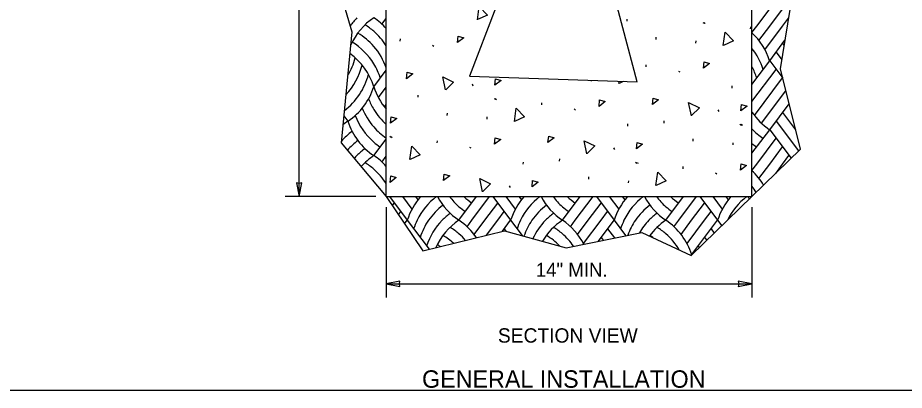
# Model space of a CAD drawing. Extents: x 99862 to 103151, y 100000 to 102076.
# Drawn here: x 101489 to 102507, y 100000 to 100427 of the extents above; entities that cross this region are included whole.
import ezdxf

# ---------------------------------------------------------------- set-up
doc = ezdxf.new("R2010")
doc.units = 0
for name, color, linetype in [('Level 1', 7, 'Continuous'), ('Level 15', 7, 'Continuous'), ('Level 17', 7, 'Continuous'), ('Level 20', 7, 'Continuous'), ('Level 21', 7, 'Continuous'), ('Level 24', 7, 'Continuous'), ('Level 25', 7, 'Continuous'), ('Level 26', 7, 'Continuous')]:
    doc.layers.add(name, color=color, linetype=linetype)

msp = doc.modelspace()

# ---------------------------------------------------------------- linework, layer by layer
at = {"layer": 'Level 1'}
msp.add_lwpolyline([(99862, 99999.5), (103151, 99999.5), (103151, 102075.5), (99862, 102075.5)], close=True, dxfattribs=at)
at = {"layer": 'Level 15'}
for p, q in [((101812.2, 100221.9), (101812.2, 100912.5)), ((101900.2, 100221.9), (101796.2, 100221.9)), ((101912.2, 100209.9), (101912.2, 100105.9)), ((102332.2, 100209.9), (102332.2, 100105.9)), ((101912.2, 100121.9), (102332.2, 100121.9))]:
    msp.add_line(p, q, dxfattribs=at)
for points in [[(101812.2, 100221.9), (101815.2, 100237.6), (101812.2, 100236.9), (101809.1, 100237.6)], [(101912.2, 100121.9), (101927.9, 100118.8), (101927.2, 100121.9), (101927.9, 100125)], [(102332.2, 100121.9), (102316.4, 100125), (102317.2, 100121.9), (102316.4, 100118.8)]]:
    msp.add_lwpolyline(points, close=True, dxfattribs=at)
at = {"layer": 'Level 17'}
for p, q in [((101912.2, 100221.9), (101912.2, 100731.9)), ((102332.2, 100221.9), (102332.2, 100731.9)), ((101912.2, 100221.9), (102332.2, 100221.9))]:
    msp.add_line(p, q, dxfattribs=at)
at = {"layer": 'Level 24'}
for points in [[(102332.2, 100221.9), (102387.8, 100276.5), (102364.8, 100368.6), (102384.3, 100489), (102366.6, 100591.7), (102387.8, 100729.7), (102366.6, 100795.2), (102391.4, 100912.1), (102348.9, 100974), (102350.7, 101089.1), (102318.8, 101124.5), (102354.2, 101152.8), (102428.5, 101131.6), (102490.5, 101205.9)], [(101819.7, 101193.6), (101909.9, 101194.2), (101897.6, 101156.4), (101925.9, 101124.5), (101888.8, 101036), (101892.3, 100959.9), (101860.4, 100862.5), (101872.8, 100775.8), (101853.4, 100678.4), (101878.1, 100591.7), (101853.4, 100476.6), (101872.8, 100411.1), (101860.4, 100283.6), (101912.2, 100221.9)], [(101902.5, 100785), (102071.1, 100725.9), (102003.2, 100572.6), (102038.2, 100439), (102007.6, 100360.2), (102200.2, 100353.6), (102167.4, 100478.4), (102257.1, 100605.5), (102184.9, 100763.1), (102351.3, 100802.6)], [(101912.2, 100221.9), (101954.2, 100159.7), (102048, 100182.7), (102118.8, 100163.2), (102205.5, 100180.9), (102262.2, 100154.4), (102332.2, 100221.9)]]:
    msp.add_lwpolyline(points, dxfattribs=at)
at = {"layer": 'Level 25'}
for p, q in [((102337.6, 100417.6), (102359.9, 100447.3)), ((102352.5, 100417.6), (102367.3, 100437.4)), ((101907.2, 100420), (101912.2, 100426.7)), ((102367.3, 100417.6), (102374.2, 100426.8)), ((102332.2, 100410.3), (102337.6, 100417.6)), ((102340.2, 100401.3), (102352.5, 100417.6)), ((102347.1, 100390.7), (102367.3, 100417.6)), ((102352.5, 100378), (102370.1, 100401.6)), ((102367.3, 100397.8), (102369.1, 100395.4)), ((102359.9, 100387.9), (102366.5, 100379.1)), ((102332.2, 100350.9), (102352.5, 100378)), ((102352.5, 100378), (102367.5, 100358)), ((101897.9, 100348.2), (101912.2, 100367.3)), ((102332.2, 100331.1), (102359.9, 100368.1)), ((102335, 100315.1), (102367.3, 100358.2)), ((101903.2, 100335.6), (101912.2, 100347.5)), ((102343.2, 100306.2), (102371.1, 100343.5)), ((102352.5, 100298.8), (102374.8, 100328.6)), ((102374.7, 100328.5), (102374.9, 100328.3)), ((101910.1, 100324.9), (101912.2, 100327.7)), ((102367.3, 100318.6), (102382.3, 100298.6)), ((101863.5, 100314.9), (101868.2, 100308.6)), ((102359.9, 100308.7), (102385.6, 100274.4)), ((102332.2, 100271.7), (102352.5, 100298.8)), ((102352.5, 100298.8), (102377.1, 100266)), ((101897.9, 100269), (101912.2, 100288.1)), ((102337.6, 100259.2), (102359.9, 100288.9)), ((102352.5, 100259.2), (102367.3, 100279)), ((101907.2, 100261.6), (101912.2, 100268.3)), ((102367.3, 100259.2), (102374.7, 100269.1)), ((102332.2, 100251.9), (102337.6, 100259.2)), ((102340.2, 100242.9), (102352.5, 100259.2)), ((102359.4, 100248.6), (102367.3, 100259.2)), ((101915.9, 100221.9), (101936.3, 100194.8)), ((101930.8, 100221.9), (101941.6, 100207.5)), ((101945.6, 100221.9), (101948.5, 100218.1)), ((101995.7, 100194.8), (102016, 100221.9)), ((102010.5, 100194.8), (102030.9, 100221.9)), ((102034.7, 100221.9), (102055, 100194.8)), ((102049.5, 100221.9), (102060.4, 100207.5)), ((102064.4, 100221.9), (102067.3, 100218.1)), ((102114.4, 100194.8), (102134.8, 100221.9)), ((102129.3, 100194.8), (102149.7, 100221.9)), ((102153.5, 100221.9), (102173.8, 100194.8)), ((102168.3, 100221.9), (102179.2, 100207.5)), ((102183.2, 100221.9), (102186.1, 100218.1)), ((102233.2, 100194.8), (102253.6, 100221.9)), ((102248.1, 100194.8), (102268.4, 100221.9)), ((102272.3, 100221.9), (102292.6, 100194.8)), ((102287.1, 100221.9), (102298, 100207.5)), ((102302, 100221.9), (102304.9, 100218.1)), ((101919.2, 100211.6), (101921.4, 100214.6)), ((102025.4, 100194.8), (102040.2, 100214.6)), ((102144.1, 100194.8), (102159, 100214.6)), ((102262.9, 100194.8), (102277.8, 100214.6)), ((101926.2, 100201.2), (101928.8, 100204.7)), ((102040.2, 100194.8), (102047.6, 100204.7)), ((102159, 100194.8), (102166.4, 100204.7)), ((102277.8, 100194.8), (102285.2, 100204.7)), ((101933.2, 100190.8), (101936.3, 100194.8)), ((101936.3, 100194.8), (101961.3, 100161.4)), ((102005, 100187.4), (102010.5, 100194.8)), ((102013.1, 100178.5), (102025.4, 100194.8)), ((102027.3, 100177.6), (102040.2, 100194.8)), ((102045.5, 100182.1), (102055, 100194.8)), ((102055, 100194.8), (102068.3, 100177.2)), ((102123.8, 100187.4), (102129.3, 100194.8)), ((102131.9, 100178.5), (102144.1, 100194.8)), ((102138.8, 100167.9), (102159, 100194.8)), ((102155.9, 100170.8), (102173.8, 100194.8)), ((102173.8, 100194.8), (102187, 100177.2)), ((102242.5, 100187.4), (102248.1, 100194.8)), ((102250.7, 100178.5), (102262.9, 100194.8)), ((102257.6, 100167.9), (102277.8, 100194.8)), ((102262.9, 100155.2), (102292.6, 100194.8)), ((102292.6, 100194.8), (102297.4, 100188.4)), ((102047.6, 100184.9), (102049.6, 100182.3)), ((102166.4, 100184.9), (102174.2, 100174.5)), ((102285.2, 100184.9), (102288.8, 100180.1)), ((102159, 100175), (102161.3, 100171.9)), ((102277.8, 100175), (102280.2, 100171.8)), ((102262.8, 100155), (102262.9, 100155.2)), ((102262.9, 100155.2), (102263, 100155.2)), ((102270.4, 100165.1), (102271.6, 100163.5))]:
    msp.add_line(p, q, dxfattribs=at)
for centre, start, end in [((101932.4, 100374.9), 135.7127, 145.0413), ((101939.8, 100365), 123.9036, 155.5486), ((101856, 100365), 41.6002, 56.0963), ((101841.1, 100345.2), 40.9413, 59.3021), ((101848.5, 100355.1), 48.9597, 58.5465), ((101848.5, 100355.1), 32.1577, 48.9597), ((102280.8, 100355.2), 17.6434, 46.9437), ((101833.7, 100335.3), 31.3316, 58.4874), ((101841.1, 100345.2), 19.0249, 40.9414), ((102273.4, 100345.3), 17.6434, 38.6012), ((101804, 100400.7), 328.4065, 345.0113), ((101826.3, 100325.4), 17.6434, 54.0098), ((101811.4, 100390.8), 316.392, 346.3199), ((101833.7, 100335.3), 17.6434, 31.3317), ((102266, 100335.4), 17.6434, 28.3216), ((101818.8, 100380.9), 307.0064, 345.7713), ((101826.3, 100371), 303.9036, 342.3566), ((101969.5, 100371), 197.6435, 220.2739), ((101962.1, 100361.1), 200.8778, 211.332), ((101954.6, 100351.2), 201.4344, 220.9416), ((101962.1, 100361.1), 211.3319, 228.3811), ((102394.4, 100361.2), 214.1019, 236.0964), ((101910.1, 100246.2), 123.9036, 129.3331), ((101939.8, 100331.4), 197.6434, 236.0964), ((101947.2, 100341.3), 200.2432, 228.9599), ((101954.6, 100351.2), 220.9415, 235.5712), ((102387, 100351.3), 223.1764, 236.0964), ((101917.5, 100236.3), 126.3063, 139.2093), ((101924.9, 100226.5), 127.1006, 139.7026), ((101947.2, 100341.3), 228.9599, 236.0964), ((102379.5, 100341.4), 230.9159, 236.0964), ((101932.4, 100216.6), 135.7127, 139.1863), ((101932.4, 100216.6), 126.331, 135.7128), ((101939.8, 100206.7), 123.9036, 138.6709), ((101856, 100206.7), 41.6002, 56.0963), ((101848.5, 100196.8), 48.9597, 58.5465), ((101848.5, 100196.8), 32.1577, 48.9597), ((102280.8, 100196.8), 30.5766, 46.9437), ((102273.4, 100186.9), 32.0375, 38.6012), ((102007.9, 100172), 138.3768, 162.3566), ((102015.3, 100162.1), 127.2549, 154.2266), ((102037.6, 100257.2), 207.959, 236.0964), ((102045, 100267.1), 216.9101, 228.9599), ((102052.4, 100277), 227.0781, 236.0964), ((102126.7, 100172), 138.3768, 162.3566), ((102134.1, 100162.1), 127.2549, 154.2266), ((102156.4, 100257.2), 207.959, 236.0964), ((102163.8, 100267.1), 216.9101, 228.9599), ((102171.2, 100277), 227.0781, 236.0964), ((102245.5, 100172), 138.3768, 162.3566), ((102252.9, 100162.1), 127.2549, 154.2266), ((102275.2, 100257.2), 207.959, 236.0964), ((102282.6, 100267.1), 216.9101, 228.9599), ((102290, 100277), 227.0781, 236.0964), ((102364.3, 100172), 138.3768, 162.3566), ((102371.7, 100162.1), 127.2549, 154.2266), ((102394, 100257.2), 207.959, 210.469), ((102022.7, 100152.2), 127.1006, 145.4911), ((102045, 100267.1), 228.9599, 236.0964), ((102141.5, 100152.2), 127.1006, 145.4911), ((102163.8, 100267.1), 228.9599, 236.0964), ((102260.3, 100152.2), 127.1006, 145.4911), ((102282.6, 100267.1), 228.9599, 236.0964), ((102030.2, 100142.3), 126.331, 135.7128), ((102148.9, 100142.3), 126.331, 135.7128), ((102267.7, 100142.3), 126.331, 135.7128), ((102015.3, 100162.1), 154.2265, 162.3566), ((102022.7, 100152.2), 145.491, 162.3566), ((102030.2, 100142.3), 135.7127, 162.3566), ((102037.6, 100132.4), 123.9036, 155.688), ((101946.3, 100122.5), 48.9597, 58.5465), ((101953.7, 100132.4), 34.3443, 56.0963), ((102134.1, 100162.1), 154.2265, 162.3566), ((102141.5, 100152.2), 145.491, 161.0901), ((102148.9, 100142.3), 135.7127, 155.2756), ((102156.4, 100132.4), 123.9036, 149.3618), ((102065.1, 100122.5), 48.9597, 58.5465), ((102072.5, 100132.4), 27.7288, 56.0963), ((102252.9, 100162.1), 154.2265, 162.3566), ((102260.3, 100152.2), 145.491, 160.1722), ((102267.7, 100142.3), 135.7127, 149.5234), ((102275.2, 100132.4), 123.9036, 143.8366), ((102183.9, 100122.5), 48.9597, 58.5465), ((102191.3, 100132.4), 17.6434, 56.0963), ((102371.7, 100162.1), 154.2265, 154.2668), ((101938.9, 100112.6), 47.8375, 59.3021), ((101946.3, 100122.5), 40.8861, 48.9597), ((102057.7, 100112.6), 44.5544, 59.3021), ((102065.1, 100122.5), 34.3765, 48.9597), ((102176.5, 100112.6), 55.8261, 59.3021), ((102183.9, 100122.5), 30.604, 48.9597), ((101931.5, 100102.7), 55.4164, 58.4874)]:
    msp.add_arc(centre, 75.2, start, end, dxfattribs=at)
at = {"layer": 'Level 26'}
for p, q in [((102188.7, 100423.3), (102188.9, 100425.9)), ((102275.9, 100422.1), (102277.4, 100421)), ((102277.1, 100421.9), (102278.6, 100420.8)), ((102330.5, 100414.5), (102330.7, 100417.1)), ((101928.2, 100400.5), (101928.4, 100403.1)), ((102222, 100402.6), (102222.2, 100405.2)), ((102267.8, 100398.2), (102268, 100400.8)), ((101965.3, 100395.9), (101966.9, 100394.7)), ((102210.6, 100370.9), (102210.8, 100373.5)), ((102247.7, 100366.2), (102249.3, 100365.1)), ((102010.7, 100351.4), (102011.7, 100349.2)), ((102147.9, 100354.6), (102148, 100355.4)), ((102309.4, 100346.4), (102309.6, 100349)), ((101948.8, 100336), (101949, 100338.6)), ((102036, 100334.8), (102037.6, 100333.7)), ((102037.2, 100334.6), (102038.8, 100333.5)), ((102090.7, 100327.2), (102090.9, 100329.8)), ((102127.8, 100322.6), (102129.4, 100321.4)), ((102293.1, 100321.7), (102294.1, 100319.6)), ((101982.2, 100315.3), (101982.4, 100317.9)), ((102028, 100310.9), (102028.2, 100313.5)), ((102231.2, 100306.4), (102231.4, 100309)), ((102189.5, 100302.8), (102189.6, 100305.4)), ((102318.4, 100305.2), (102320, 100304.1)), ((102319.6, 100305), (102321.2, 100303.9)), ((101916.1, 100291.2), (101917.7, 100290.1)), ((101917.3, 100291), (101918.9, 100289.9)), ((102264.6, 100285.6), (102264.8, 100288.2)), ((101970.8, 100283.6), (101971, 100286.2)), ((102007.9, 100278.9), (102009.4, 100277.8)), ((102173.1, 100278.1), (102174.2, 100275.9)), ((102310.4, 100281.3), (102310.6, 100283.9)), ((102069.5, 100259.1), (102069.7, 100261.7)), ((102111.3, 100262.7), (102111.5, 100265.3)), ((102198.5, 100261.6), (102200.1, 100260.4)), ((102199.7, 100261.3), (102201.3, 100260.2)), ((102253.2, 100253.9), (102253.3, 100256.5)), ((102290.3, 100249.3), (102291.8, 100248.1)), ((102144.7, 100242), (102144.9, 100244.6)), ((102190.5, 100237.6), (102190.7, 100240.2)), ((102053.2, 100234.4), (102054.3, 100232.3))]:
    msp.add_line(p, q, dxfattribs=at)
for points in [[(102016.8, 100425.1), (102018.9, 100440.3), (102028.4, 100430.5), (102017, 100425.2)], [(102299.2, 100395.4), (102301.3, 100410.7), (102310.8, 100400.8), (102299.4, 100395.5)], [(101994, 100398.9), (101994.7, 100406.3), (102001.1, 100404.3), (101994, 100398.9)], [(102276.4, 100369.3), (102277.1, 100376.6), (102283.5, 100374.7), (102276.4, 100369.3)], [(101935.5, 100357.4), (101936.2, 100364.7), (101942.6, 100362.8), (101935.5, 100357.4)], [(101980.2, 100344.5), (101977, 100359.5), (101989.4, 100353.5), (101980.5, 100344.7)], [(102037, 100350), (102037.8, 100357.3), (102044.1, 100355.4), (102037, 100350)], [(102179.3, 100351.8), (102179.6, 100354.3)], [(102184.4, 100354.1), (102179.5, 100351.9)], [(102156.5, 100325.6), (102157.2, 100333), (102163.6, 100331.1), (102156.5, 100325.6)], [(102217.9, 100327.7), (102218.6, 100335.1), (102225, 100333.1), (102217.9, 100327.7)], [(102262.6, 100314.9), (102259.4, 100329.9), (102271.8, 100323.9), (102262.8, 100315)], [(102059.4, 100308.2), (102061.5, 100323.4), (102071, 100313.5), (102059.6, 100308.2)], [(102319.4, 100320.3), (102320.2, 100327.7), (102326.5, 100325.7), (102319.4, 100320.3)], [(101917.1, 100306.3), (101917.9, 100313.7), (101924.2, 100311.7), (101917.1, 100306.3)], [(102036.6, 100282), (102037.3, 100289.3), (102043.7, 100287.4), (102036.6, 100282)], [(102097.9, 100284.1), (102098.7, 100291.4), (102105, 100289.5), (102097.9, 100284.1)], [(101939.4, 100264.5), (101941.5, 100279.7), (101951.1, 100269.9), (101939.7, 100264.6)], [(102142.7, 100271.2), (102139.5, 100286.2), (102151.8, 100280.2), (102142.9, 100271.4)], [(102199.5, 100276.7), (102200.3, 100284), (102206.6, 100282.1), (102199.5, 100276.7)], [(102318.9, 100252.3), (102319.7, 100259.7), (102326, 100257.8), (102318.9, 100252.3)], [(101978, 100240.4), (101978.8, 100247.8), (101985.1, 100245.8), (101978, 100240.4)], [(102221.8, 100234.9), (102223.9, 100250.1), (102233.5, 100240.2), (102222.1, 100234.9)], [(101916.6, 100238.3), (101917.4, 100245.7), (101923.7, 100243.8), (101916.6, 100238.3)], [(102022.8, 100227.6), (102019.6, 100242.6), (102031.9, 100236.6), (102023, 100227.7)], [(102079.6, 100233), (102080.3, 100240.4), (102086.7, 100238.4), (102079.6, 100233)]]:
    msp.add_lwpolyline(points, dxfattribs=at)

# ---------------------------------------------------------------- texts
at = {"layer": 'Level 20'}
msp.add_text('14" MIN.', height=16, dxfattribs=at).set_placement((102083.9, 100129.9))
at = {"layer": 'Level 21'}
for s, height, p in [('SECTION VIEW', 16.5, (102040.4, 100054.2)), ('GENERAL INSTALLATION', 20, (101953.3, 100002.4))]:
    msp.add_text(s, height=height, dxfattribs=at).set_placement(p)

doc.saveas('drawing.dxf')
